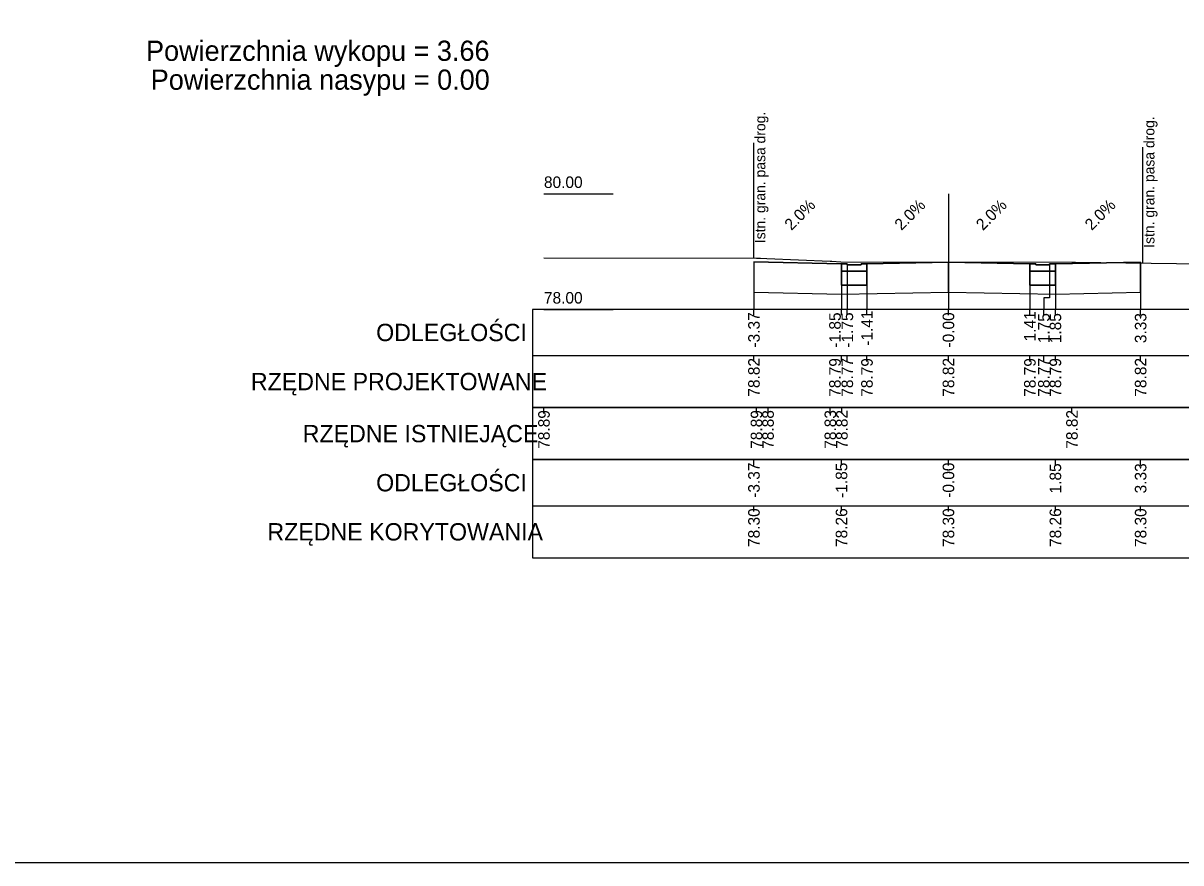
# Model space of a CAD drawing. Extents: x 7492871 to 7493499, y 5802964 to 5802992.
# Drawn here: x 7493391.54 to 7493411.57, y 5802963.88 to 5802978.41 of the extents above; entities that cross this region are included whole.
import ezdxf

# ---------------------------------------------------------------- set-up
doc = ezdxf.new("R2010")
doc.units = 0
for name, color, linetype in [('_wydruk', 7, 'Continuous'), ('d_pop_nasyp_opis', 7, 'Continuous'), ('d_pop_wykop_opis', 7, 'Continuous'), ('opisy_ramki_pop', 7, 'Continuous'), ('pop_comp_kostka', 7, 'Continuous'), ('pop_comp_lawa', 7, 'Continuous'), ('pop_comp_scieralna', 7, 'Continuous'), ('pop_granica_istn', 7, 'Continuous'), ('pop_opis', 7, 'Continuous'), ('pop_os', 7, 'Continuous'), ('pop_teren', 7, 'Continuous')]:
    doc.layers.add(name, color=color, linetype=linetype)

msp = doc.modelspace()

# ---------------------------------------------------------------- linework, layer by layer
msp.add_lwpolyline([(7493404.182, 5802974.279), (7493405.697, 5802974.248), (7493405.797, 5802974.248), (7493405.798, 5802974.228), (7493406.037, 5802974.228), (7493406.038, 5802974.248), (7493406.138, 5802974.248), (7493407.548, 5802974.277), (7493408.958, 5802974.248), (7493409.058, 5802974.248), (7493409.059, 5802974.228), (7493409.298, 5802974.228), (7493409.299, 5802974.248), (7493409.399, 5802974.248), (7493410.874, 5802974.278)])
at = {"layer": '_wydruk'}
msp.add_lwpolyline([(7492871.369, 5802992.281), (7493499.283, 5802992.281), (7493499.283, 5802963.881), (7492871.369, 5802963.881)], close=True, dxfattribs=at)
at = {"layer": 'opisy_ramki_pop'}
for points in [[(7493404.182, 5802973.759), (7493404.182, 5802973.659), (7493404.182, 5802973.659), (7493404.182, 5802973.459)], [(7493407.548, 5802973.757), (7493407.548, 5802973.659), (7493407.548, 5802973.659), (7493407.548, 5802973.459)], [(7493410.874, 5802973.758), (7493410.874, 5802973.659), (7493410.874, 5802973.659), (7493410.874, 5802973.459)], [(7493405.697, 5802973.719), (7493405.697, 5802973.659), (7493405.697, 5802973.659), (7493405.697, 5802973.459)], [(7493409.399, 5802973.719), (7493409.399, 5802973.659), (7493409.399, 5802973.659), (7493409.399, 5802973.459)]]:
    msp.add_lwpolyline(points, dxfattribs=at)
at = {"layer": 'pop_comp_kostka'}
for p, q in [((7493405.797, 5802974.248), (7493405.697, 5802974.248)), ((7493405.697, 5802974.248), (7493405.697, 5802974.118)), ((7493405.798, 5802974.228), (7493405.797, 5802974.248)), ((7493406.037, 5802974.228), (7493405.798, 5802974.228)), ((7493406.038, 5802974.248), (7493406.037, 5802974.228)), ((7493406.138, 5802974.248), (7493406.038, 5802974.248)), ((7493406.138, 5802974.118), (7493406.138, 5802974.248)), ((7493409.058, 5802974.248), (7493408.958, 5802974.248)), ((7493408.958, 5802974.248), (7493408.958, 5802974.118)), ((7493409.059, 5802974.228), (7493409.058, 5802974.248)), ((7493409.298, 5802974.228), (7493409.059, 5802974.228)), ((7493409.299, 5802974.248), (7493409.298, 5802974.228)), ((7493409.399, 5802974.248), (7493409.299, 5802974.248)), ((7493409.399, 5802974.118), (7493409.399, 5802974.248)), ((7493405.697, 5802974.118), (7493406.138, 5802974.118)), ((7493408.958, 5802974.118), (7493409.399, 5802974.118))]:
    msp.add_line(p, q, dxfattribs=at)
at = {"layer": 'pop_comp_lawa'}
for p, q in [((7493406.138, 5802974.118), (7493405.697, 5802974.118)), ((7493405.697, 5802974.118), (7493405.697, 5802973.878)), ((7493406.138, 5802973.878), (7493406.138, 5802974.118)), ((7493409.399, 5802974.118), (7493408.958, 5802974.118)), ((7493408.958, 5802974.118), (7493408.958, 5802973.878)), ((7493409.399, 5802973.878), (7493409.399, 5802974.118)), ((7493405.697, 5802973.878), (7493406.138, 5802973.878)), ((7493408.958, 5802973.878), (7493409.399, 5802973.878))]:
    msp.add_line(p, q, dxfattribs=at)
at = {"layer": 'pop_comp_scieralna'}
for p, q in [((7493405.697, 5802974.248), (7493404.182, 5802974.279)), ((7493404.182, 5802974.279), (7493404.182, 5802973.759)), ((7493405.697, 5802973.878), (7493405.697, 5802974.248)), ((7493407.548, 5802974.277), (7493406.138, 5802974.248)), ((7493406.138, 5802974.248), (7493406.138, 5802973.878)), ((7493407.548, 5802973.757), (7493407.548, 5802974.277)), ((7493408.958, 5802974.248), (7493407.548, 5802974.277)), ((7493407.548, 5802974.277), (7493407.548, 5802973.757)), ((7493408.958, 5802973.878), (7493408.958, 5802974.248)), ((7493410.874, 5802974.278), (7493409.399, 5802974.248)), ((7493409.399, 5802974.248), (7493409.399, 5802973.878)), ((7493410.874, 5802973.758), (7493410.874, 5802974.278)), ((7493404.182, 5802973.759), (7493405.697, 5802973.719)), ((7493406.138, 5802973.878), (7493405.697, 5802973.878)), ((7493405.697, 5802973.719), (7493407.548, 5802973.757)), ((7493407.548, 5802973.757), (7493409.399, 5802973.719)), ((7493409.399, 5802973.878), (7493408.958, 5802973.878)), ((7493409.399, 5802973.719), (7493410.874, 5802973.758))]:
    msp.add_line(p, q, dxfattribs=at)
at = {"layer": 'pop_granica_istn'}
for p, q in [((7493404.182, 5802974.843), (7493404.182, 5802976.343)), ((7493410.915, 5802974.763), (7493410.915, 5802976.263)), ((7493404.182, 5802974.343), (7493404.182, 5802974.843)), ((7493410.915, 5802974.263), (7493410.915, 5802974.763))]:
    msp.add_line(p, q, dxfattribs=at)
at = {"layer": 'pop_opis'}
for p, q in [((7493400.548, 5802975.459), (7493401.748, 5802975.459)), ((7493400.348, 5802973.459), (7493400.348, 5802971.759)), ((7493400.348, 5802973.459), (7493400.348, 5802971.759)), ((7493400.348, 5802973.459), (7493400.348, 5802971.759)), ((7493400.348, 5802973.459), (7493400.348, 5802971.759)), ((7493400.548, 5802973.459), (7493401.748, 5802973.459)), ((7493404.182, 5802973.359), (7493404.182, 5802973.459)), ((7493405.697, 5802973.359), (7493405.697, 5802973.459)), ((7493405.798, 5802973.359), (7493405.798, 5802973.459)), ((7493406.138, 5802973.359), (7493406.138, 5802973.459)), ((7493407.548, 5802973.359), (7493407.548, 5802973.459)), ((7493408.958, 5802973.359), (7493408.958, 5802973.459)), ((7493409.199, 5802973.359), (7493409.199, 5802973.459)), ((7493409.399, 5802973.359), (7493409.399, 5802973.459)), ((7493410.874, 5802973.359), (7493410.874, 5802973.459)), ((7493400.348, 5802972.659), (7493414.748, 5802972.659)), ((7493400.348, 5802972.659), (7493414.748, 5802972.659)), ((7493400.348, 5802972.659), (7493414.748, 5802972.659)), ((7493400.348, 5802972.659), (7493414.748, 5802972.659)), ((7493404.182, 5802972.559), (7493404.182, 5802972.659)), ((7493405.697, 5802972.559), (7493405.697, 5802972.659)), ((7493405.798, 5802972.559), (7493405.798, 5802972.659)), ((7493406.138, 5802972.559), (7493406.138, 5802972.659)), ((7493407.548, 5802972.559), (7493407.548, 5802972.659)), ((7493408.958, 5802972.559), (7493408.958, 5802972.659)), ((7493409.199, 5802972.559), (7493409.199, 5802972.659)), ((7493409.399, 5802972.559), (7493409.399, 5802972.659)), ((7493410.874, 5802972.559), (7493410.874, 5802972.659)), ((7493400.348, 5802971.759), (7493400.348, 5802970.859)), ((7493400.548, 5802971.659), (7493400.548, 5802971.759)), ((7493404.226, 5802971.659), (7493404.226, 5802971.759)), ((7493404.426, 5802971.659), (7493404.426, 5802971.759)), ((7493405.504, 5802971.659), (7493405.504, 5802971.759)), ((7493405.704, 5802971.659), (7493405.704, 5802971.759)), ((7493409.686, 5802971.659), (7493409.686, 5802971.759)), ((7493400.348, 5802970.859), (7493400.348, 5802969.159)), ((7493404.182, 5802970.759), (7493404.182, 5802970.859)), ((7493405.697, 5802970.759), (7493405.697, 5802970.859)), ((7493407.548, 5802970.759), (7493407.548, 5802970.859)), ((7493409.399, 5802970.759), (7493409.399, 5802970.859)), ((7493410.874, 5802970.759), (7493410.874, 5802970.859)), ((7493400.348, 5802970.059), (7493414.748, 5802970.059)), ((7493404.182, 5802969.959), (7493404.182, 5802970.059)), ((7493405.697, 5802969.959), (7493405.697, 5802970.059)), ((7493407.548, 5802969.959), (7493407.548, 5802970.059)), ((7493409.399, 5802969.959), (7493409.399, 5802970.059)), ((7493410.874, 5802969.959), (7493410.874, 5802970.059))]:
    msp.add_line(p, q, dxfattribs=at)
for points in [[(7493404.182, 5802974.279), (7493404.182, 5802973.659), (7493404.182, 5802973.659), (7493404.182, 5802973.459)], [(7493405.697, 5802974.248), (7493405.697, 5802973.659), (7493405.697, 5802973.659), (7493405.697, 5802973.459)], [(7493405.798, 5802974.228), (7493405.798, 5802973.659), (7493405.798, 5802973.659), (7493405.798, 5802973.459)], [(7493406.138, 5802974.248), (7493406.138, 5802973.659), (7493406.138, 5802973.659), (7493406.138, 5802973.459)], [(7493407.548, 5802974.277), (7493407.548, 5802973.659), (7493407.548, 5802973.659), (7493407.548, 5802973.459)], [(7493408.958, 5802974.248), (7493408.958, 5802973.659), (7493408.958, 5802973.659), (7493408.958, 5802973.459)], [(7493409.298, 5802974.228), (7493409.298, 5802973.659), (7493409.199, 5802973.659), (7493409.199, 5802973.459)], [(7493409.399, 5802974.248), (7493409.399, 5802973.659), (7493409.399, 5802973.659), (7493409.399, 5802973.459)], [(7493410.874, 5802974.278), (7493410.874, 5802973.659), (7493410.874, 5802973.659), (7493410.874, 5802973.459)]]:
    msp.add_lwpolyline(points, dxfattribs=at)
for points in [[(7493400.348, 5802973.459), (7493400.348, 5802971.759), (7493414.748, 5802971.759), (7493414.748, 5802973.459)], [(7493400.348, 5802973.459), (7493400.348, 5802971.759), (7493414.748, 5802971.759), (7493414.748, 5802973.459)], [(7493400.348, 5802973.459), (7493400.348, 5802971.759), (7493414.748, 5802971.759), (7493414.748, 5802973.459)], [(7493400.348, 5802973.459), (7493400.348, 5802971.759), (7493414.748, 5802971.759), (7493414.748, 5802973.459)], [(7493400.348, 5802971.759), (7493400.348, 5802970.859), (7493414.748, 5802970.859), (7493414.748, 5802971.759)], [(7493400.348, 5802970.859), (7493400.348, 5802969.159), (7493414.748, 5802969.159), (7493414.748, 5802970.859)]]:
    msp.add_lwpolyline(points, close=True, dxfattribs=at)
at = {"layer": 'pop_os'}
msp.add_line((7493407.548, 5802975.459), (7493407.548, 5802973.459), dxfattribs=at)
at = {"layer": 'pop_teren'}
msp.add_lwpolyline([(7493400.548, 5802974.353), (7493404.226, 5802974.344), (7493404.298, 5802974.343), (7493404.405, 5802974.339), (7493405.504, 5802974.292), (7493405.532, 5802974.291), (7493405.684, 5802974.28), (7493409.686, 5802974.278), (7493409.717, 5802974.278), (7493409.745, 5802974.278), (7493414.548, 5802974.214)], dxfattribs=at)

# ---------------------------------------------------------------- texts
at = {"layer": 'd_pop_nasyp_opis'}
msp.add_text('Powierzchnia nasypu = 0.00', height=0.35, dxfattribs=at).set_placement((7493393.743, 5802977.259))
at = {"layer": 'd_pop_wykop_opis'}
msp.add_text('Powierzchnia wykopu = 3.66', height=0.35, dxfattribs=at).set_placement((7493393.661, 5802977.759))
at = {"layer": 'pop_granica_istn'}
for p in [(7493404.38, 5802974.604), (7493411.113, 5802974.524)]:
    msp.add_text('Istn. gran. pasa drog.', height=0.18, rotation=90, dxfattribs=at).set_placement(p)
at = {"layer": 'pop_opis'}
for s, height, p in [('80.00', 0.2, (7493400.548, 5802975.559)), ('78.00', 0.2, (7493400.548, 5802973.559)), ('ODLEGŁOŚCI', 0.3, (7493397.644, 5802972.909)), ('ODLEGŁOŚCI', 0.3, (7493397.644, 5802972.909)), ('ODLEGŁOŚCI', 0.3, (7493397.644, 5802972.909)), ('ODLEGŁOŚCI', 0.3, (7493397.644, 5802972.909)), ('RZĘDNE PROJEKTOWANE', 0.3, (7493395.476, 5802972.059)), ('RZĘDNE PROJEKTOWANE', 0.3, (7493395.476, 5802972.059)), ('RZĘDNE PROJEKTOWANE', 0.3, (7493395.476, 5802972.059)), ('RZĘDNE PROJEKTOWANE', 0.3, (7493395.476, 5802972.059)), ('RZĘDNE ISTNIEJĄCE', 0.3, (7493396.373, 5802971.159)), ('ODLEGŁOŚCI', 0.3, (7493397.644, 5802970.309)), ('RZĘDNE KORYTOWANIA', 0.3, (7493395.762, 5802969.459))]:
    msp.add_text(s, height=height, dxfattribs=at).set_placement(p)
for s, rotation, p in [('2.0%', 45, (7493404.831, 5802974.813)), ('2.0%', 45, (7493406.735, 5802974.812)), ('2.0%', 45, (7493408.145, 5802974.812)), ('2.0%', 45, (7493410.028, 5802974.813)), ('-3.37', 90, (7493404.282, 5802972.798)), ('-1.85', 90, (7493405.684, 5802972.796)), ('-1.75', 90, (7493405.898, 5802972.796)), ('-1.41', 90, (7493406.238, 5802972.829)), ('-0.00', 90, (7493407.648, 5802972.798)), ('1.41', 90, (7493409.058, 5802972.905)), ('1.75', 90, (7493409.299, 5802972.873)), ('1.85', 90, (7493409.499, 5802972.873)), ('3.33', 90, (7493410.974, 5802972.874)), ('78.82', 90, (7493404.282, 5802971.948)), ('78.79', 90, (7493405.684, 5802971.946)), ('78.77', 90, (7493405.898, 5802971.947)), ('78.79', 90, (7493406.238, 5802971.946)), ('78.82', 90, (7493407.648, 5802971.948)), ('78.79', 90, (7493409.058, 5802971.946)), ('78.77', 90, (7493409.299, 5802971.947)), ('78.79', 90, (7493409.499, 5802971.946)), ('78.82', 90, (7493410.974, 5802971.948)), ('78.89', 90, (7493400.648, 5802971.046)), ('78.89', 90, (7493404.326, 5802971.046)), ('78.88', 90, (7493404.526, 5802971.046)), ('78.83', 90, (7493405.604, 5802971.047)), ('78.82', 90, (7493405.804, 5802971.048)), ('78.82', 90, (7493409.786, 5802971.048)), ('-3.37', 90, (7493404.282, 5802970.198)), ('-1.85', 90, (7493405.797, 5802970.196)), ('-0.00', 90, (7493407.648, 5802970.198)), ('1.85', 90, (7493409.499, 5802970.273)), ('3.33', 90, (7493410.974, 5802970.274)), ('78.30', 90, (7493404.282, 5802969.347)), ('78.26', 90, (7493405.797, 5802969.347)), ('78.30', 90, (7493407.648, 5802969.347)), ('78.26', 90, (7493409.499, 5802969.347)), ('78.30', 90, (7493410.974, 5802969.347))]:
    msp.add_text(s, height=0.2, rotation=rotation, dxfattribs=at).set_placement(p)

doc.saveas('drawing.dxf')
